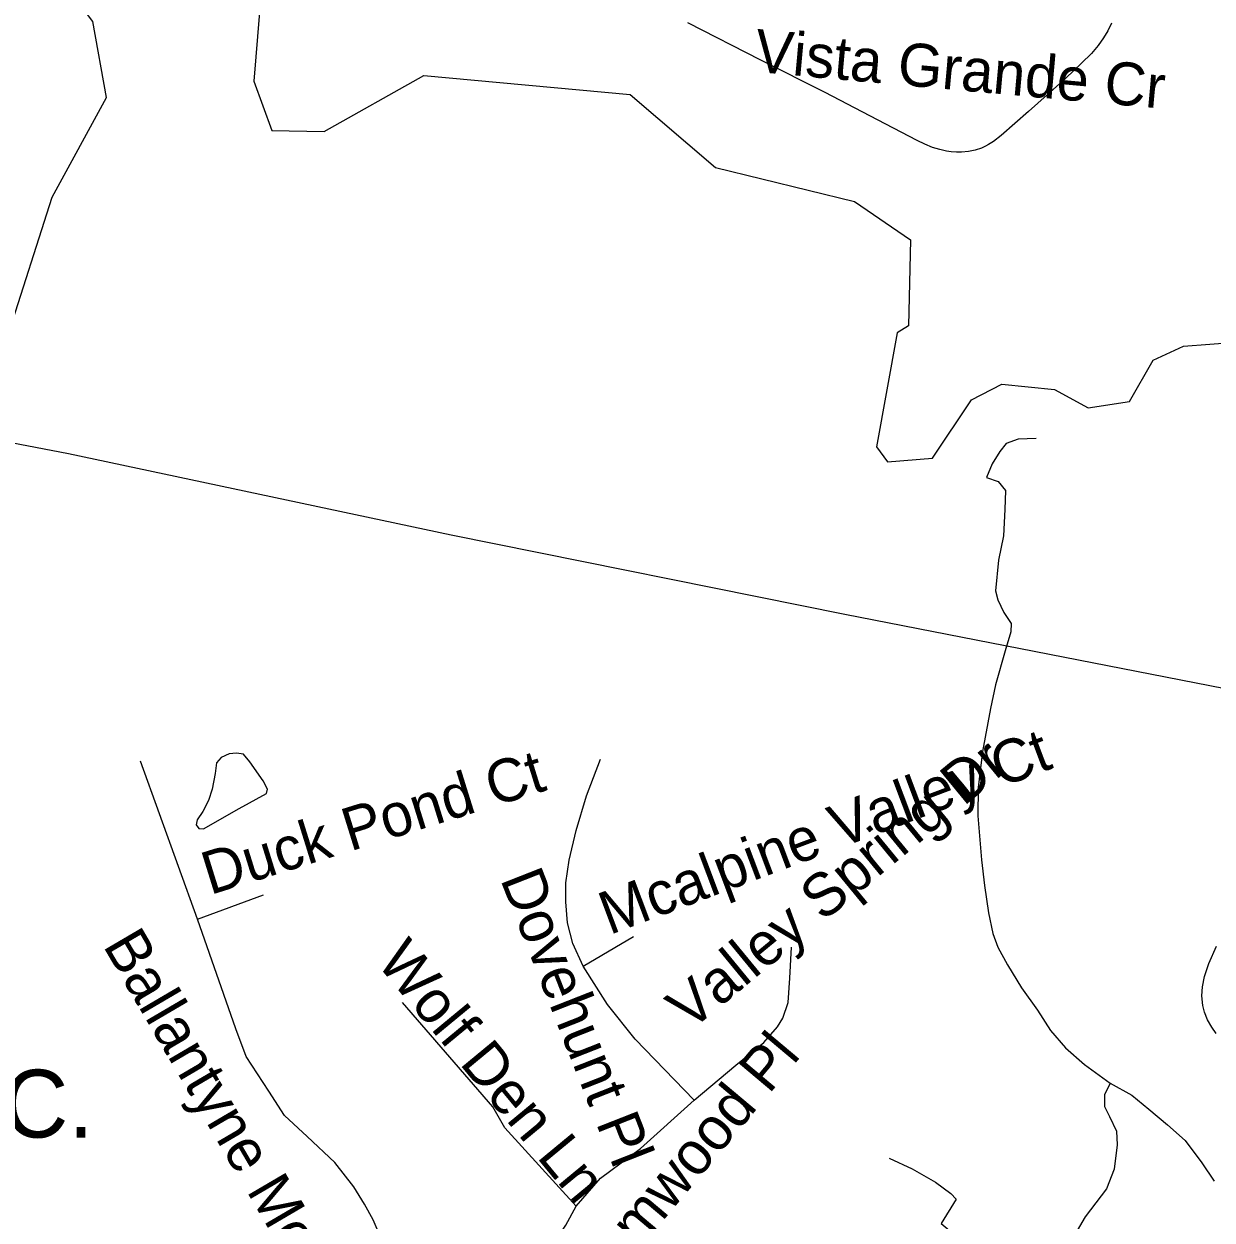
# Model space of a CAD drawing. Extents: x 1383679 to 1536984, y 460658 to 651027.
# Drawn here: x 1440347 to 1442977, y 480512 to 483158 of the extents above; entities that cross this region are included whole.
import ezdxf

# ---------------------------------------------------------------- set-up
doc = ezdxf.new("R2010")
doc.units = 0
for name, color, linetype in [('Exist Cultural Church Label', 7, 'Continuous'), ('Exist Hydrographic Creek Single Shore', 7, 'Continuous'), ('Exist Hydrographic Misc Water Feature', 7, 'Continuous'), ('Exist Road Non-System Type 51', 7, 'Continuous'), ('Exist Road Non-System Type 51 Label', 7, 'Continuous'), ('Exist Utilities Electrical Transmission Line', 7, 'Continuous')]:
    doc.layers.add(name, color=color, linetype=linetype)

msp = doc.modelspace()

# ---------------------------------------------------------------- linework, layer by layer
at = {"layer": 'Exist Hydrographic Creek Single Shore'}
for points in [[(1439010.2, 482392.6), (1439125.1, 482304.9), (1439359.2, 482333.1), (1440060.1, 482322.2), (1440227.2, 482384.5), (1440312.2, 482468.2), (1440410.2, 482774.7), (1440530.1, 482995.5), (1440500.1, 483163.5), (1440085.2, 483713.5), (1439826.2, 484142.1), (1439844.1, 484233.6), (1440036.2, 484206.8), (1440128.1, 484247.7), (1440255.2, 484376.3), (1440331.1, 484417.5), (1440714.2, 484403.2)], [(1440877.2, 483283.9), (1440856.2, 483031.6), (1440896.2, 482922.5), (1441012.1, 482920.2), (1441232.1, 483043.7), (1441689.2, 483001.7), (1441878.1, 482840.4), (1442185.1, 482765.3), (1442309.2, 482680.7), (1442305.2, 482490.4), (1442280.2, 482474.5), (1442234.1, 482222.7), (1442258.1, 482189.4), (1442358.2, 482197.2), (1442444.2, 482326.8), (1442511.1, 482361.5), (1442628.1, 482349.3), (1442702.2, 482308.5), (1442794.1, 482323), (1442846.2, 482413.9), (1442913.1, 482445.4), (1443088.2, 482458.2)]]:
    msp.add_lwpolyline(points, dxfattribs=at)
at = {"layer": 'Exist Hydrographic Misc Water Feature'}
for points in [[(1442587.3, 482240.9), (1442547.3, 482239.2), (1442521, 482229.9), (1442506.8, 482212.2), (1442490.1, 482184.6), (1442477.6, 482154.5)], [(1442477.6, 482154.5), (1442503.6, 482145.8), (1442519.2, 482125.7), (1442518.4, 482083.9), (1442515.4, 482025.7), (1442504.4, 481971.8), (1442497.1, 481903.8), (1442502.8, 481884), (1442516.2, 481855.8), (1442531.8, 481831.7), (1442531.6, 481813.6), (1442518.6, 481771.3), (1442497.3, 481696.2), (1442486.3, 481643.9), (1442468.6, 481548.3), (1442459.2, 481468.9), (1442458, 481406.5), (1442466.3, 481308.7), (1442473.2, 481251.9), (1442482, 481191.8), (1442491.2, 481145.7), (1442502.7, 481115.9), (1442524.1, 481076.9), (1442555.1, 481026.2), (1442590.2, 480976.3), (1442619.4, 480931.4), (1442652.6, 480893), (1442694.1, 480856.1), (1442751.3, 480814.7)], [(1440801.7, 481543.2), (1440783.6, 481535.4), (1440773.3, 481523.3), (1440771, 481499.6), (1440764.3, 481465.2), (1440755.8, 481439.9), (1440743.4, 481415.6), (1440731, 481397.8), (1440728.8, 481386.3), (1440734.8, 481378), (1440744.7, 481377.8), (1440823.6, 481422.2), (1440884.3, 481455.4), (1440886.3, 481465.2), (1440876.7, 481483.5), (1440847.5, 481525.9), (1440833.7, 481542.6), (1440817.8, 481544.6), (1440801.7, 481543.2)], [(1442751.3, 480814.7), (1442738.8, 480789.5), (1442738.4, 480763.2), (1442749.9, 480740.9), (1442765.4, 480708.5), (1442766.9, 480678.9), (1442759.8, 480625), (1442743.1, 480581), (1442695.9, 480519.6), (1442662.9, 480462.8), (1442642.3, 480432.8), (1442611.8, 480407.2), (1442571.1, 480374.3), (1442542.7, 480348.7), (1442530.4, 480332.5), (1442515.8, 480296.7), (1442499.1, 480257.7), (1442481.9, 480197.3), (1442473, 480147.4), (1442475.8, 480080), (1442466.6, 480013.8), (1442451, 479930.3), (1442447.5, 479848.4)], [(1442751.3, 480814.7), (1442798.8, 480788.3), (1442836.4, 480757.2), (1442877.7, 480722.7), (1442917.1, 480688.3), (1442954.2, 480639.1), (1442981.4, 480598.3)]]:
    msp.add_lwpolyline(points, dxfattribs=at)
at = {"layer": 'Exist Road Non-System Type 51'}
for points in [[(1442754.5, 483160), (1442746, 483142.8), (1442736.3, 483127.2), (1442724.5, 483110.3), (1442710.1, 483092.7), (1442688.1, 483071.1), (1442653, 483038.2), (1442570.7, 482964.5), (1442510.3, 482911.4), (1442492.7, 482897.9), (1442482.1, 482891.3), (1442475, 482887.3), (1442466.3, 482883.4), (1442452.8, 482878.7), (1442437.9, 482875.9), (1442422.5, 482874.2), (1442410.9, 482874.2), (1442399, 482875.1), (1442389.2, 482876.4), (1442374.3, 482880.1), (1442358.2, 482885), (1442340.9, 482891.9), (1442324.2, 482900.1), (1442219.3, 482955), (1442120.5, 483006.1), (1441978, 483077.5), (1441816.5, 483160.7)], [(1440731.9, 481177.7), (1440605.1, 481527.6)], [(1441585, 481073.8), (1441561.9, 481123.8), (1441550.4, 481170), (1441546.5, 481216.1), (1441546.5, 481258.4), (1441554.2, 481308.4), (1441569.6, 481373.8), (1441592.6, 481450.7), (1441623.4, 481531.5)], [(1440731.9, 481177.7), (1440877.9, 481231.5)], [(1441350.6, 480189.4), (1441289.1, 480250.9), (1441235.3, 480316.3), (1441193, 480377.8), (1441146.9, 480450.9), (1441120, 480512.4), (1441100.8, 480547), (1441077.7, 480585.5), (1441035.5, 480639.3), (1440974, 480697), (1440924, 480743.1), (1440889.4, 480797), (1440839.5, 480873.9), (1440816.4, 480935.4), (1440731.9, 481177.7)], [(1441585, 481073.8), (1441696.4, 481139.2)], [(1441830.9, 480777.7), (1441923.1, 480854.7), (1441984.6, 480904.6), (1442015.3, 480939.3), (1442026.9, 480958.5), (1442038.4, 480993.1), (1442042.2, 481046.9), (1442046.1, 481116.1)], [(1442986.1, 480924.8), (1442976.2, 480938.8), (1442966.4, 480955.3), (1442959.6, 480971.9), (1442956.4, 480987.1), (1442954.4, 481008.3), (1442955.6, 481028.2), (1442959.6, 481050.8), (1442969.6, 481079.9), (1442986.6, 481117.9)], [(1441830.9, 480777.7), (1441700.2, 480912.3), (1441638.8, 480989.2), (1441585, 481073.8)], [(1441569.6, 480543.2), (1441412, 480716.2), (1441385.1, 480762.4), (1441185.3, 480993.1)], [(1441569.6, 480543.2), (1441623.4, 480604.7), (1441711.8, 480670.1), (1441830.9, 480777.7)], [(1442261.8, 480649.4), (1442313.1, 480625.4), (1442364.6, 480595.8), (1442398.5, 480570.7), (1442410.1, 480558.5), (1442377, 480504.5), (1442390.2, 480493.5), (1442412.4, 480470.3), (1442424.9, 480445.8), (1442441, 480406.4), (1442458.6, 480368.9), (1442470.8, 480350.2), (1442492.8, 480323.8), (1442529.1, 480289.5), (1442567.8, 480252.1), (1442615.4, 480200.8), (1442646, 480168.2)], [(1441350.6, 480189.4), (1441396.7, 480239.4), (1441438.9, 480297.1), (1441473.5, 480362.4), (1441492.7, 480408.6), (1441515.8, 480454.7), (1441546.5, 480500.9), (1441569.6, 480543.2)]]:
    msp.add_lwpolyline(points, dxfattribs=at)
at = {"layer": 'Exist Utilities Electrical Transmission Line'}
msp.add_lwpolyline([(1433072.2, 483712.7), (1433651.4, 483595.3), (1434400.2, 483437.8), (1435069.4, 483299.8), (1435881.8, 483131), (1436509.1, 483004.1), (1437148.5, 482868.8), (1437781.8, 482737.8), (1438363.1, 482613.6), (1438773.3, 482521.1), (1439016.5, 482483.7), (1439560.8, 482377.7), (1440446, 482207.6), (1441293.1, 482028.1), (1442164.2, 481852.1), (1443035.6, 481682.1), (1443460.2, 481596.3), (1443946.4, 481483.5), (1444590.1, 481343.7), (1444822.1, 481229.4), (1445208.7, 481032.3), (1445379.2, 480953), (1445787.7, 480753.5), (1446059.4, 480620.6)], dxfattribs=at)

# ---------------------------------------------------------------- texts
at = {"layer": 'Exist Cultural Church Label'}
msp.add_text('Ministries INC.', height=150, rotation=0, dxfattribs=at).set_placement((1439197.4, 480694.7))
at = {"layer": 'Exist Road Non-System Type 51 Label'}
for s, rotation, p in [('Vista Grande Cr', 354.8299, (1441961.7, 483052.4)), ('Mcalpine Valley Ct', 20.6357, (1441643.1, 481142.2)), ('Valley Spring Dr', 39.4267, (1441821, 480928.2)), ('Duck Pond Ct', 17.3072, (1440759.3, 481230.8)), ('Dovehunt Pl', 291.4548, (1441400.8, 481266.6)), ('Ballantyne Meadows Dr', 300.3697, (1440521.1, 481119.6)), ('Wolf Den Ln', 309.5583, (1441125.3, 481081.8)), ('Grahamwood Pl', 49.9792, (1441482.8, 480178))]:
    msp.add_text(s, height=95, rotation=rotation, dxfattribs=at).set_placement(p)

doc.saveas('drawing.dxf')
